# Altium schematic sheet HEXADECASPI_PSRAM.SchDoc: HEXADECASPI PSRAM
size A4; Date: Not used; ApprovedBy: Not used; CheckedBy: Not used; Author: Not used; CompanyName: STMicroelectronics; DrawnBy: Not used; Engineer: Not used; Organization: Not used; Address1: Not used; Address2: Not used; Address3: Not used; Address4: Not used; DocumentNumber: Not used; Revision: Not used; SheetNumber: 7; SheetTotal: 16
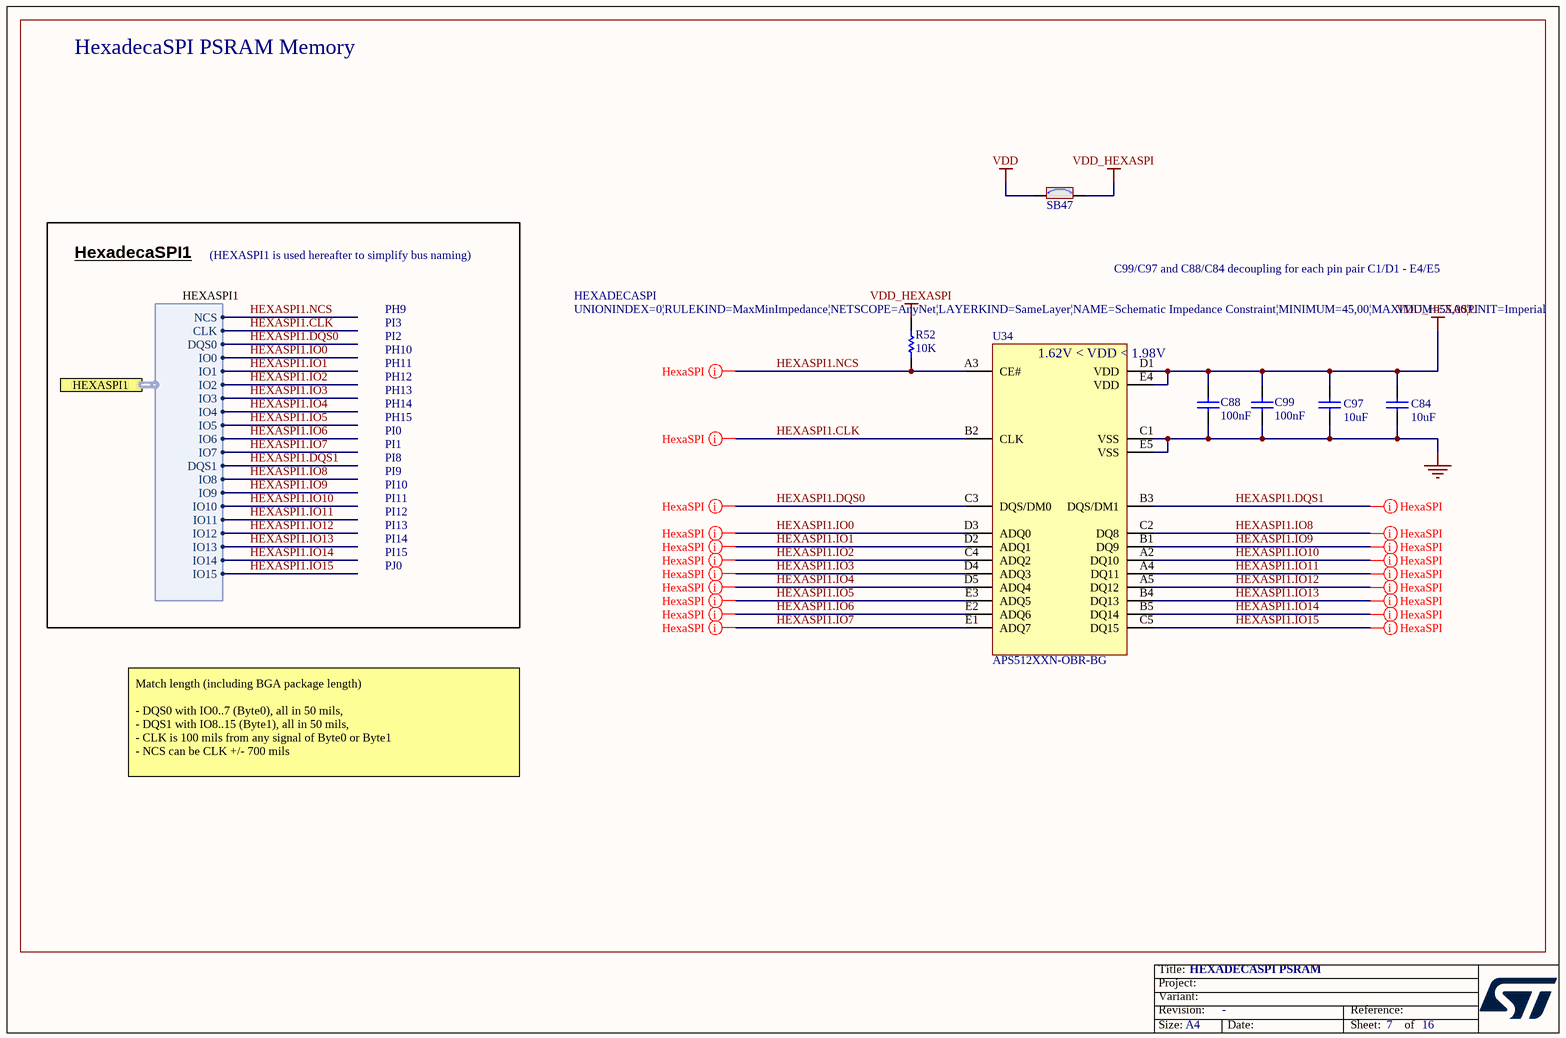
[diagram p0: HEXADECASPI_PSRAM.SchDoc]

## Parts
C84  value 10uF  [C0603_H0P8]  (hidden comment: Capacitor)
C88  value 100nF  [C0402]  (hidden comment: Capacitor)
C97  value 10uF  [C0603_H0P8]  (hidden comment: Capacitor)
C99  value 100nF  [C0402]  (hidden comment: Capacitor)
R52  value 10K  [R0402]  (hidden comment: Resistor)
SB47  SB_ON  [SOLDER-BRIDGE_R0402-0R]  (value not drawn)
U34  value APS512XXN-OBR-BG  [ICC_BGA24_5X5-BALL-ARRAY_6X8_P1]  (hidden comment: APS256XXN-OBR-BG)

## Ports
HEXASPI1 (harness HEXASPI1)

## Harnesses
HEXASPI1: IO1, IO0, DQS0, NCS, IO2, IO3, IO5, IO4, IO6, IO7, CLK, DQS1, IO8, IO9, IO10, IO11, IO12, IO13, IO14, IO15

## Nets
GND: C84.1 C88.1 C97.1 C99.1 U34.C1(VSS) U34.E5(VSS)
VDD: SB47.1
VDD_HEXASPI: C84.2 C88.2 C97.2 C99.2 R52.2 SB47.2 U34.D1(VDD) U34.E4(VDD)
HEXASPI1.CLK: U34.B2(CLK) ; port HEXASPI1.CLK
HEXASPI1.DQS0: U34.C3(DQS/DM0) ; port HEXASPI1.DQS0
HEXASPI1.DQS1: U34.B3(DQS/DM1) ; port HEXASPI1.DQS1
HEXASPI1.IO0: U34.D3(ADQ0) ; port HEXASPI1.IO0
HEXASPI1.IO1: U34.D2(ADQ1) ; port HEXASPI1.IO1
HEXASPI1.IO2: U34.C4(ADQ2) ; port HEXASPI1.IO2
HEXASPI1.IO3: U34.D4(ADQ3) ; port HEXASPI1.IO3
HEXASPI1.IO4: U34.D5(ADQ4) ; port HEXASPI1.IO4
HEXASPI1.IO5: U34.E3(ADQ5) ; port HEXASPI1.IO5
HEXASPI1.IO6: U34.E2(ADQ6) ; port HEXASPI1.IO6
HEXASPI1.IO7: U34.E1(ADQ7) ; port HEXASPI1.IO7
HEXASPI1.IO8: U34.C2(DQ8) ; port HEXASPI1.IO8
HEXASPI1.IO9: U34.B1(DQ9) ; port HEXASPI1.IO9
HEXASPI1.IO10: U34.A2(DQ10) ; port HEXASPI1.IO10
HEXASPI1.IO11: U34.A4(DQ11) ; port HEXASPI1.IO11
HEXASPI1.IO12: U34.A5(DQ12) ; port HEXASPI1.IO12
HEXASPI1.IO13: U34.B4(DQ13) ; port HEXASPI1.IO13
HEXASPI1.IO14: U34.B5(DQ14) ; port HEXASPI1.IO14
HEXASPI1.IO15: U34.C5(DQ15) ; port HEXASPI1.IO15
HEXASPI1.NCS: R52.1 U34.A3(CE#) ; port HEXASPI1.NCS

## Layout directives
rule Matched Net Lengths [Tolerance = 1000mil]; net class HEXASPI; rule Impedance Constraint [Min = 50.00    Max = 60.00    ]; rule Routing Layers [TopLayer - Enabled BottomLayer - Disabled]: HEXASPI1.NCS
rule Matched Net Lengths [Tolerance = 20mil]; net class HEXASPI; rule Impedance Constraint [Min = 45.00    Max = 55.00    ]; rule Routing Layers [TopLayer - Enabled BottomLayer - Disabled]: HEXASPI1.DQS1, HEXASPI1.IO0, HEXASPI1.IO1, HEXASPI1.IO2, HEXASPI1.IO3, HEXASPI1.IO4, HEXASPI1.IO5, HEXASPI1.IO6, HEXASPI1.IO7, HEXASPI1.IO8, HEXASPI1.IO9, HEXASPI1.IO10, HEXASPI1.IO11, HEXASPI1.IO12, HEXASPI1.IO13, HEXASPI1.IO14, HEXASPI1.IO15
rule Matched Net Lengths [Tolerance = 20mil]; net class HEXADECASPI; rule Impedance Constraint [Min = 45.00    Max = 55.00    ]; rule Routing Layers [TopLayer - Enabled BottomLayer - Disabled]: HEXASPI1.CLK
rule Matched Net Lengths [Tolerance = 20mil]; net class HEXASPI; rule Impedance Constraint [Min = 50.00    Max = 60.00    ]; rule Routing Layers [TopLayer - Enabled BottomLayer - Disabled]: HEXASPI1.DQS0

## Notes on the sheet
- HexadecaSPI PSRAM Memory
- HexadecaSPI1
- (HEXASPI1 is used hereafter to simplify bus naming)
- PH9
- C99/C97 and C88/C84 decoupling for each pin pair C1/D1 - E4/E5
- PH10
- PH11
- PH12
- PI2
- PI3
- 1.62V < VDD < 1.98V
- PH13
- PH14
- PH15
- PI0
- PI1
- PI8
- PI9
- PI10
- PI11
- PI12
- PI13
- PI14
- PI15
- PJ0
- Match length (including BGA package length)
  - DQS0 with IO0..7 (Byte0), all in 50 mils,
  - DQS1 with IO8..15 (Byte1), all in 50 mils,
  - CLK is 100 mils from any signal of Byte0 or Byte1
  - NCS can be CLK +/- 700 mils

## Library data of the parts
C84 C97 = MCD-02605: Capacitor, MLCC, 10uF, 10V, X5R, +/-10%, 0603, T=0.8mm; Manufacturer_Part_Number: CC0603KRX5R6BB106; Manufacturer: YAGEO; Part_Preference: Recommended; Order_Code_RS: 2006536; ShowFields: YES; ID: 4711
C88 C99 = MCD-00006: Capacitor, MLCC, 100nF, 16V, X7R, +/-10%, 0402, T=0.5mm; Manufacturer_Part_Number: CC0402KRX7R7BB104; Manufacturer: YAGEO; Part_Preference: Recommended; Order_Code_RS: 616-9701; Component_Country_Of_Origin: China
R52 = MCD-00053: Resistor, 10K, 0402, +/-1%, 1/16W; Manufacturer_Part_Number: RC0402FR-0710KL; Manufacturer: YAGEO; BMS_Part_Number: 9131590; Part_Preference: Recommended; Component_Country_Of_Origin: China
SB47 = MCD-01618: Solder Bridge 0402 ON; Part_Type: Misc; Manufacturer_Part_Number: RC0402JR-070RL; Manufacturer: YAGEO; Part_Preference: Recommended; Order_Code_RS: 618-5804; Component_Country_Of_Origin: China
U34 = MCD-02904: Memory,Hexa-SPI-PSRAM,512Mb,x8x16,200MHz,1.8V,DDR,BGA24, PASR LVCMOS; Part_Type: IC; Manufacturer: AP MEMORY TECHNOLOGY CORP.; Part_Preference: Recommended; ShowFields: YES; ID: 5020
